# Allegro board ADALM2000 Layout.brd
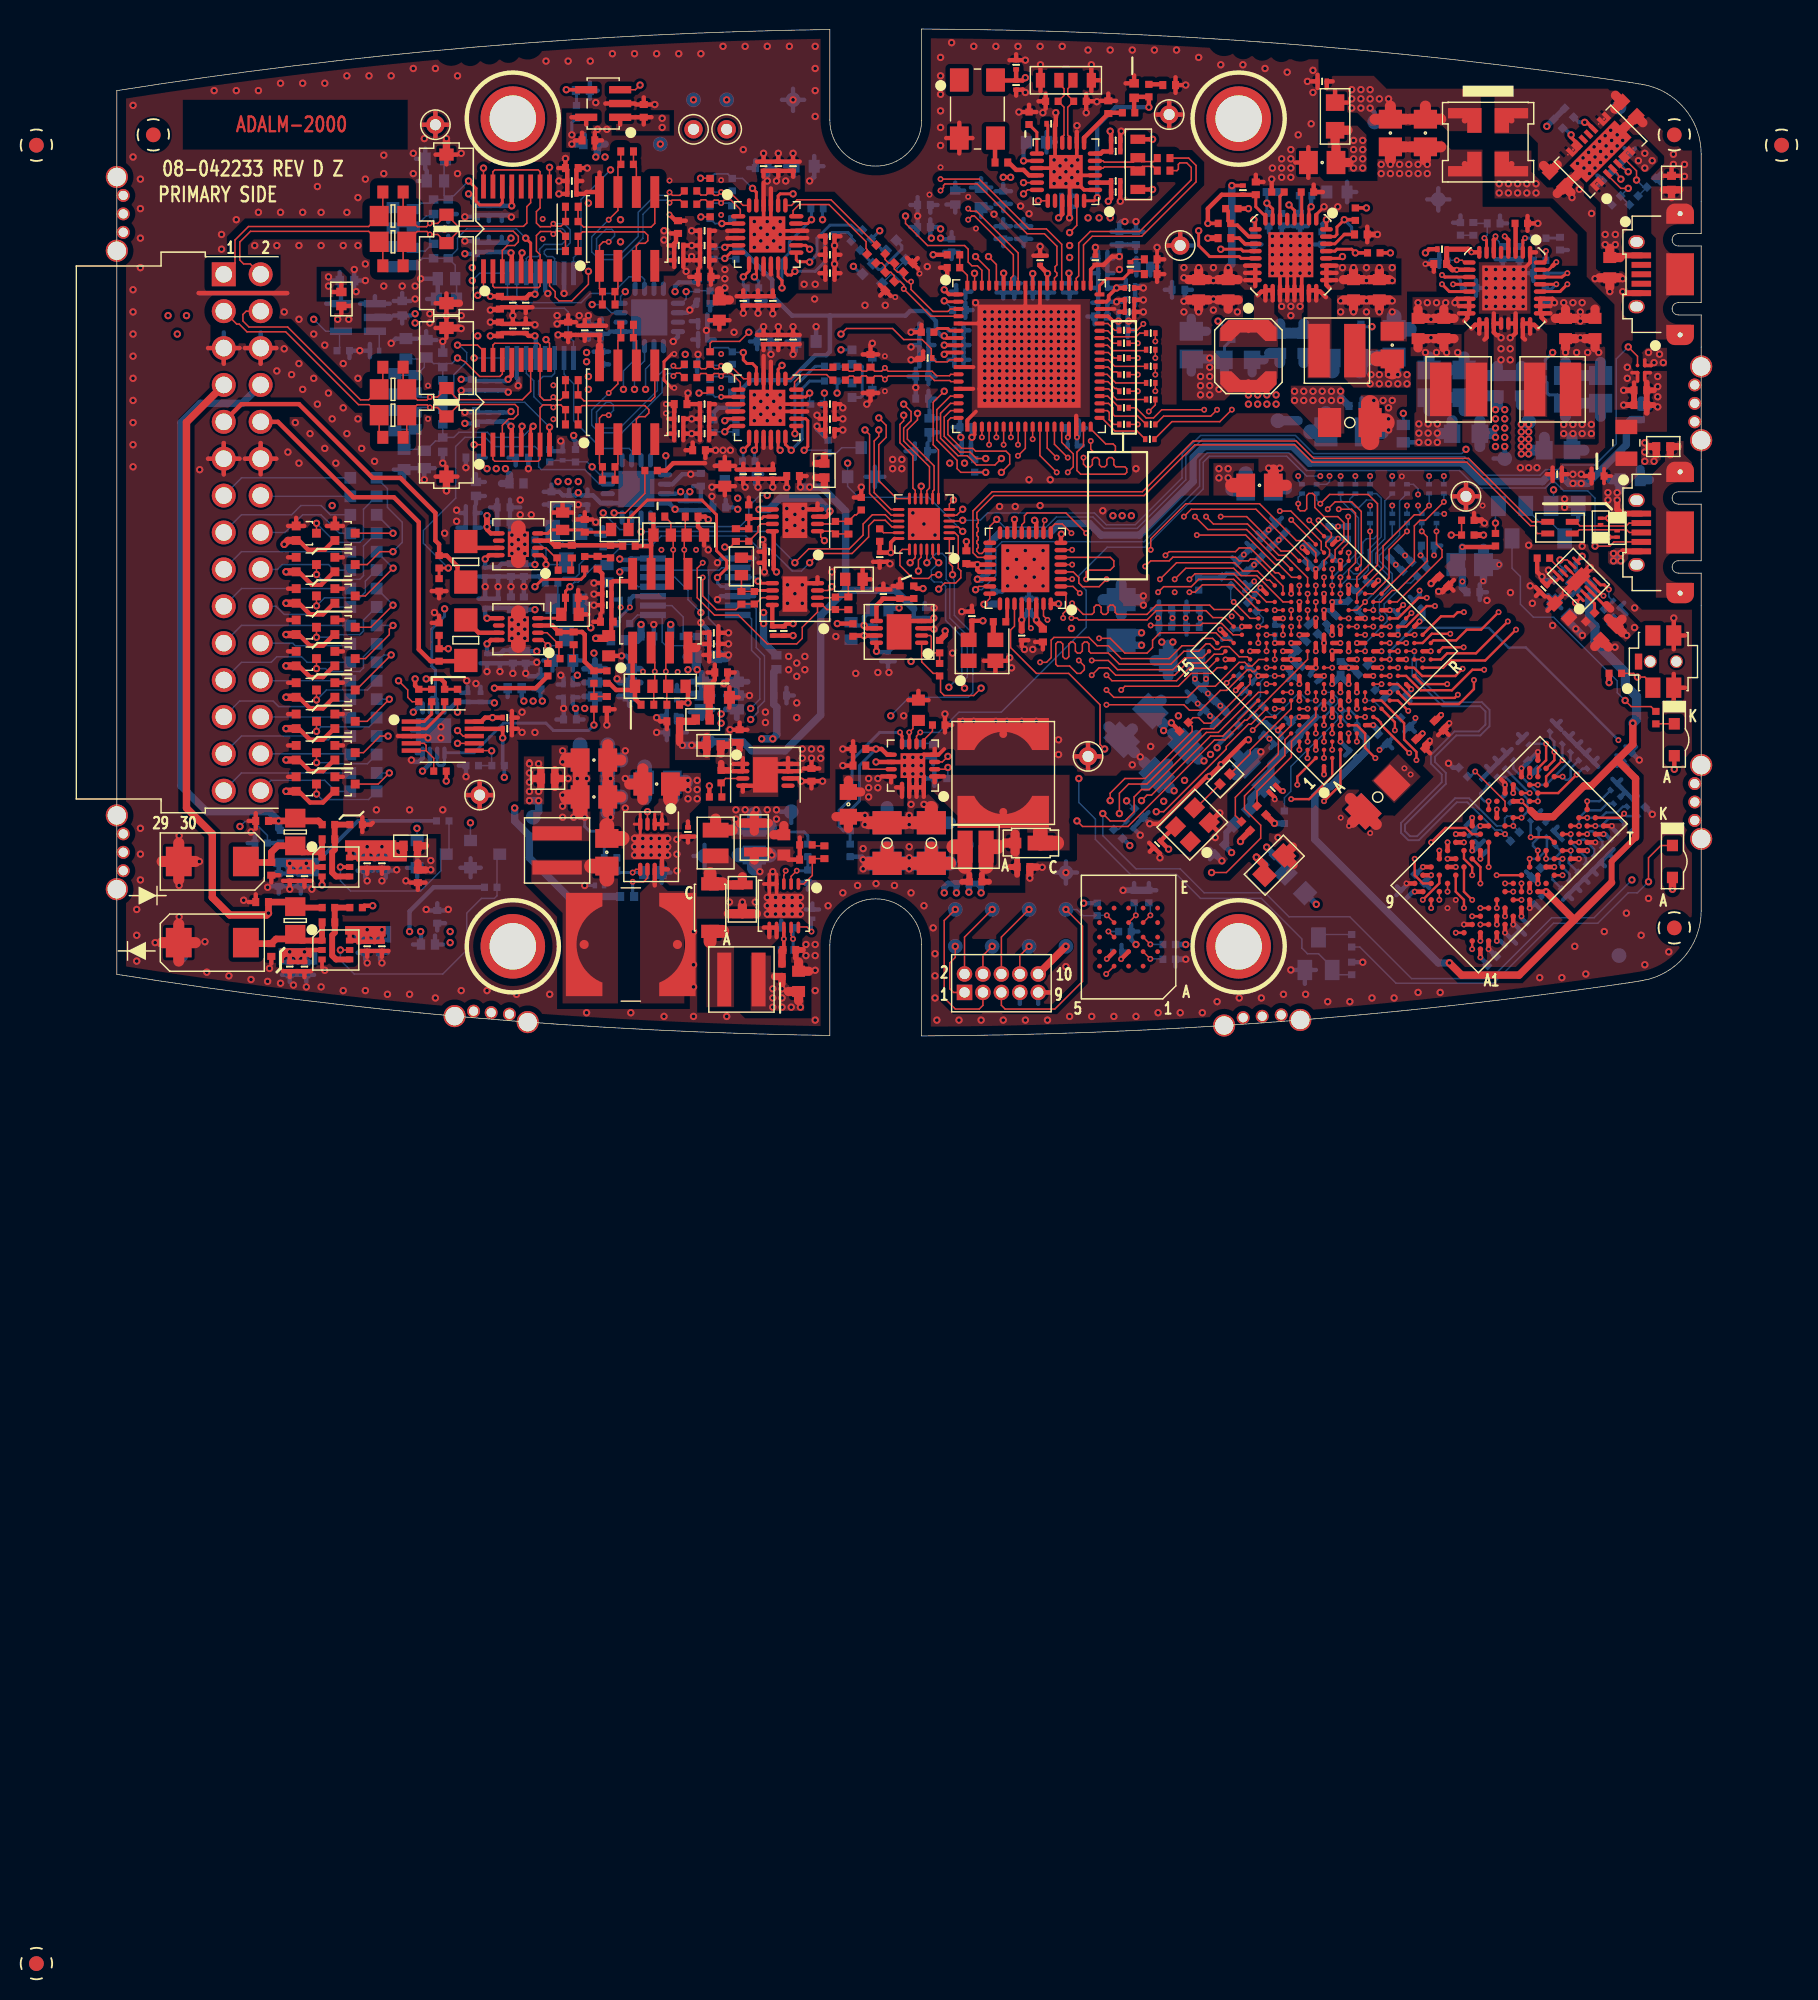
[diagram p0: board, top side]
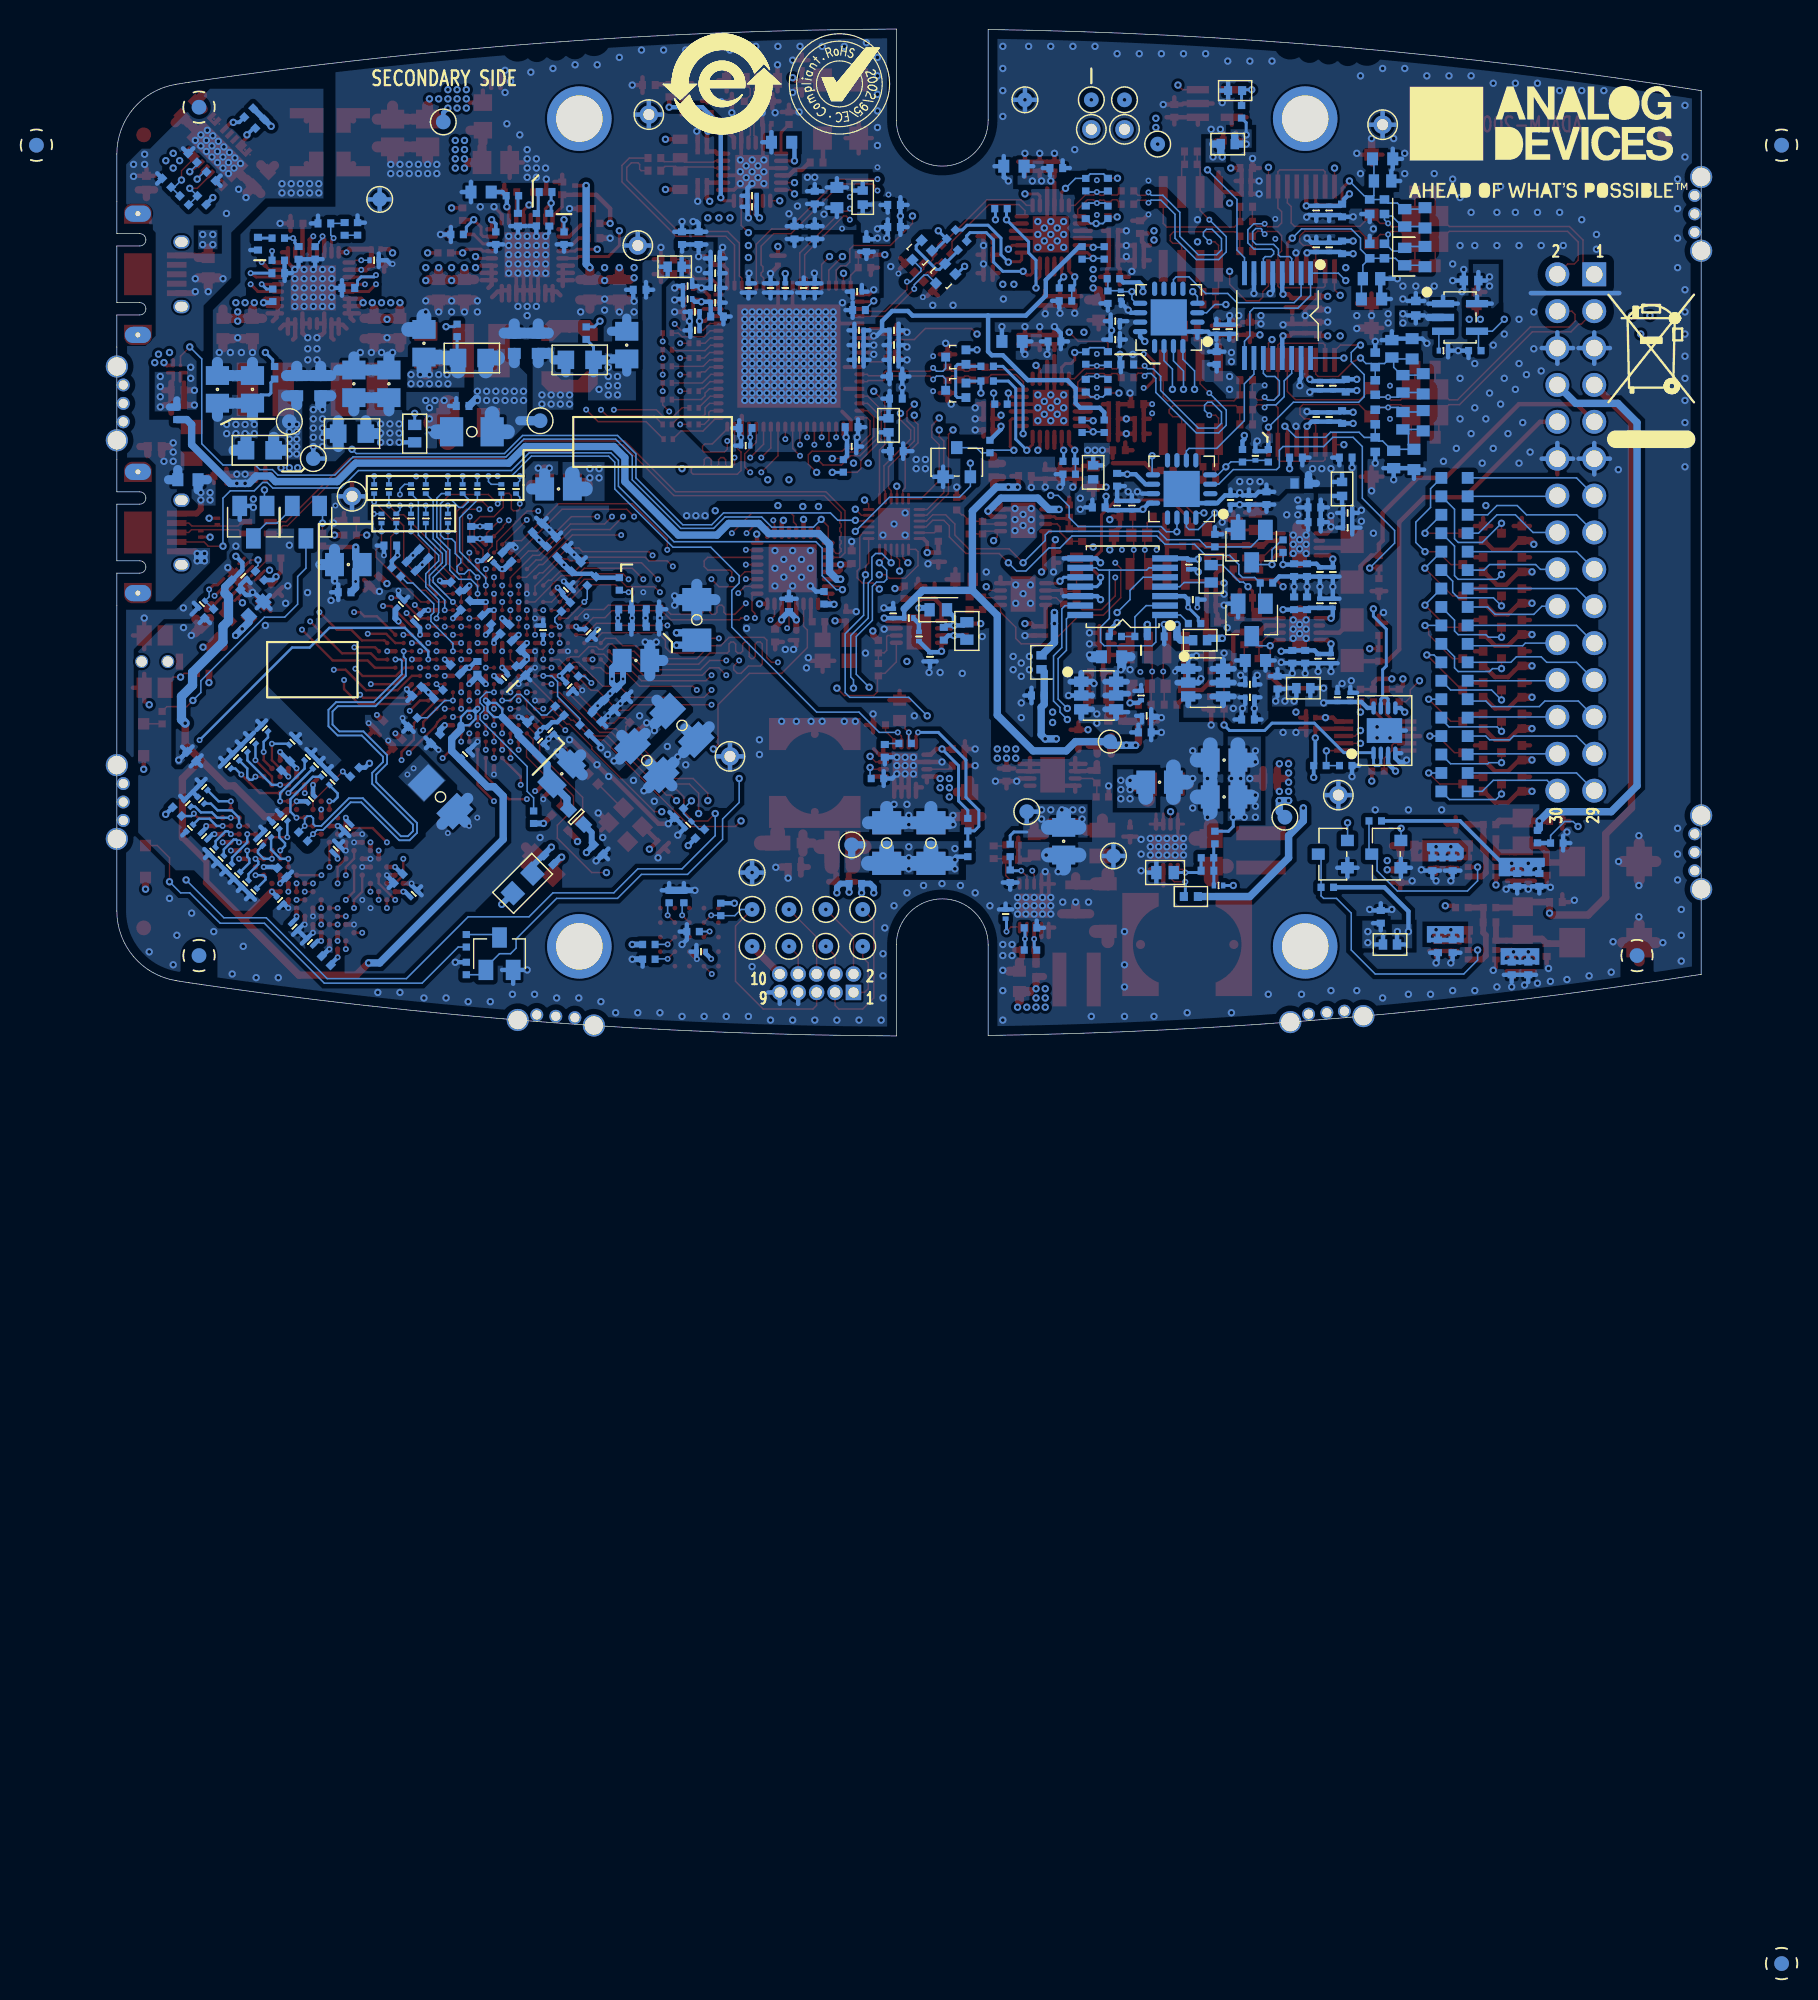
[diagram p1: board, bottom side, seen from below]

Outline 109.14 x 69.34 mm; copper layers: TOP, L2_GND, L3_PWR, L4_GND, L5_SIG, L6_SIG, L7_GND, L8_PWR, L9_GND, BOTTOM. Coordinates in mm from the lower left corner of the outline.
Outline path: 0,65.1 arc(24.48,68.08) 49.11,69.31 49.11,63.06 arc(52.28,59.9) 55.44,63.06 55.44,69.34 arc(79.87,68.37) 104.18,65.67 105.05,65.53 arc(107.98,63.88) 109.14,60.73 109.14,57.47 109.14,55.25 107.56,55.25 arc(107.26,55.12) 107.14,54.82 arc(107.26,54.52) 107.56,54.4 109.14,54.4 109.14,50.5 107.56,50.5 arc(107.26,50.37) 107.14,50.07 arc(107.26,49.77) 107.56,49.65 109.14,49.65 109.14,37.47 107.56,37.47 arc(107.26,37.34) 107.14,37.04 arc(107.26,36.74) 107.56,36.62 109.14,36.62 109.14,32.72 107.56,32.72 arc(107.26,32.59) 107.14,32.29 arc(107.26,31.99) 107.56,31.87 109.14,31.87 109.14,29.65 109.14,8.61 arc(107.98,5.45) 105.05,3.81 104.18,3.67 arc(79.87,0.97) 55.44,0 55.44,6.28 arc(52.28,9.44) 49.11,6.28 49.11,0.03 arc(24.48,1.26) 0,4.24 0,65.1

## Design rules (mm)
constraint set DEFAULT: min track width 0.102
net group ADC_SC1_N: nets ADC_SC1_N UNNAMED_31_ADA49402V2_I232__5
net group ADC_SC1_P: nets ADC_SC1_P UNNAMED_31_ADA49402V2_I232__4
net group ADC_SC2_N: nets ADC_SC2_N UNNAMED_32_ADA49402V2_I190__4
net group ADC_SC2_P: nets ADC_SC2_P UNNAMED_32_ADA49402V2_I190__5
net group DAC_AVG1: nets DAC_AVG1_N DAC_AVG1_P
net group DAC_AVG2: nets DAC_AVG2_N DAC_AVG2_P
net group DDR3_CK: nets DDR3_CK_N DDR3_CK_P
net group DDR3_DQS0: nets DDR3_DQS0_N DDR3_DQS0_P
net group DDR3_DQS1: nets DDR3_DQS1_N DDR3_DQS1_P
net group DP1: nets UNNAMED_31_ADG202N_I2_S UNNAMED_31_ADG202N_I19_S
net group DP4: nets UNNAMED_31_AD8066_I6_OUT UNNAMED_31_AD8066_I55_OUT
net group DP5: nets UNNAMED_31_ADA49402V2_I232__1 UNNAMED_31_ADA49402V2_I232__3
net group IN_1: nets UNNAMED_32_ADG202N_I25_S UNNAMED_32_ADG202N_I34_S
net group IN_1C: nets UNNAMED_32_AD8066_I42_OUT UNNAMED_32_AD8066_I82_OUT
net group IN_1D: nets UNNAMED_32_ADA49402V2_I190__1 UNNAMED_32_ADA49402V2_I190__2
net group IN_SC1: nets IN_SC1_N IN_SC1_P
net group IN_SC2: nets IN_SC2_N IN_SC2_P
net group MASTER_CLK_N: nets MASTER_CLK_N UNNAMED_36_ADF43609_I40_RFOUTB
net group MASTER_CLK_P: nets MASTER_CLK_P UNNAMED_36_ADF43609_I40_RFOUTA
net group PWR: nets VCCPLL VTTVREF
net group RX_CLK: nets RX_CLK UNNAMED_30_AD9963_I47_TRXCLK
net group RXD_0: nets RXD_0 UNNAMED_30_AD9963_I47_TRXD0
net group RXD_1: nets RXD_1 UNNAMED_30_AD9963_I47_TRXD1
net group RXD_2: nets RXD_2 UNNAMED_30_AD9963_I47_TRXD2
net group RXD_3: nets RXD_3 UNNAMED_30_AD9963_I47_TRXD3
net group RXD_4: nets RXD_4 UNNAMED_30_AD9963_I47_TRXD4
net group RXD_5: nets RXD_5 UNNAMED_30_AD9963_I47_TRXD5
net group RXD_6: nets RXD_6 UNNAMED_30_AD9963_I47_TRXD6
net group RXD_7: nets RXD_7 UNNAMED_30_AD9963_I47_TRXD7
net group RXD_8: nets RXD_8 UNNAMED_30_AD9963_I47_TRXD8
net group RXD_9: nets RXD_9 UNNAMED_30_AD9963_I47_TRXD9
net group RXD_10: nets RXD_10 UNNAMED_30_AD9963_I47_TRXD10
net group RXD_11: nets RXD_11 UNNAMED_30_AD9963_I47_TRXD11
net group RXIQ: nets RXIQ UNNAMED_30_AD9963_I47_TRXIQ
net group TX_CLK: nets TX_CLK UNNAMED_30_AD9963_I47_TXCLK
net group TXD_0: nets TXD_0 UNNAMED_30_AD9963_I47_TXD0
net group TXD_1: nets TXD_1 UNNAMED_30_AD9963_I47_TXD1
net group TXD_2: nets TXD_2 UNNAMED_30_AD9963_I47_TXD2
net group TXD_3: nets TXD_3 UNNAMED_30_AD9963_I47_TXD3
net group TXD_4: nets TXD_4 UNNAMED_30_AD9963_I47_TXD4
net group TXD_5: nets TXD_5 UNNAMED_30_AD9963_I47_TXD5
net group TXD_6: nets TXD_6 UNNAMED_30_AD9963_I47_TXD6
net group TXD_7: nets TXD_7 UNNAMED_30_AD9963_I47_TXD7
net group TXD_8: nets TXD_8 UNNAMED_30_AD9963_I47_TXD8
net group TXD_9: nets TXD_9 UNNAMED_30_AD9963_I47_TXD9
net group TXD_10: nets TXD_10 UNNAMED_30_AD9963_I47_TXD10
net group TXD_11: nets TXD_11 UNNAMED_30_AD9963_I47_TXD11
net group TXIQ: nets TXIQ UNNAMED_30_AD9963_I47_TXIQ
net group UART: nets UART_RX UART_TX
net group UNNAMED_31_AD8066_I6_NINV: nets UNNAMED_31_AD8066_I6_NINV UNNAMED_31_ADG202N_I19_D
net group UNNAMED_31_AD8066_I55_NINV: nets UNNAMED_31_AD8066_I55_NINV UNNAMED_31_ADG202N_I1_D
net group UNNAMED_32_AD8066_I42_NINV: nets UNNAMED_32_AD8066_I42_NINV UNNAMED_32_ADG202N_I164_S
net group UNNAMED_32_AD8066_I82_NINV: nets UNNAMED_32_AD8066_I82_NINV UNNAMED_32_ADG202N_I163_S
net group USB2: nets UNNAMED_45_CHOKE4P_I331_N2 UNNAMED_45_CHOKE4P_I331_N3
net group USB_OTG: nets USB_OTG_N USB_OTG_P
net group JTAG: nets JTAG_TCK JTAG_TDI JTAG_TDO JTAG_TMS
net group QSPI: nets PS_MIO01_500_QSPI0_SS_B PS_MIO02_500_QSPI0_IO0 PS_MIO03_500_QSPI0_IO1 PS_MIO04_500_QSPI0_IO2 PS_MIO05_500_QSPI0_IO3 PS_MIO06_500_QSPI0_SCLK
net group USB_ULPI: nets PS_MIO28_501_USB0_D4 PS_MIO29_501_USB0_DIR PS_MIO30_501_USB0_STP PS_MIO31_501_USB0_NXT PS_MIO32_501_USB0_D0 PS_MIO33_501_USB0_D1 PS_MIO34_501_USB0_D2 PS_MIO35_501_USB0_D3 PS_MIO36_501_USB0_CLK PS_MIO37_501_USB0_D5 PS_MIO38_501_USB0_D6 PS_MIO39_501_USB0_D7

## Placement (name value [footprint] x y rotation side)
A1  ADG612YRUZ  [TSSOP16]  27.53 43.63 0 top
A2  ADG611YRUZ  [TSSOP16]  29.18 49.6 0 bottom
A3  AD8066ARZ  [SO8]  35.15 55.57 0 top
A4  ADG612YRUZ  [TSSOP16]  27.53 55.57 0 top
A5  AD8066ARZ  [SO8]  35.15 43.63 0 top
A6  AD8657ACPZ  [QFN8_3X3_PAD2_44X1_7]  46.71 30.43 90 top
A7  AD8000YCPZ-R2  [QFN8_3X3_PAD1_75X1_45]  27.66 28.01 90 top
A8  AD8657ACPZ  [QFN8_3X3_PAD2_44X1_7]  46.71 35.51 90 top
A9  AD8000YCPZ-R2  [QFN8_3X3_PAD1_75X1_45]  27.66 33.86 90 top
A10  AD8058ARZ  [SO8]  37.44 29.28 0 top
A11  AD8657ACPZ  [QFN8_3X3_PAD2_44X1_7]  53.88 27.82 90 top
A12  ADA4805-1AKSZ  [SC70-6]  15.09 11.63 270 top
A13  AD8657ACPZ  [QFN8_3X3_PAD2_44X1_7]  21.82 21.03 180 bottom
A14  ADA4805-1AKSZ  [SC70-6]  15.09 5.92 270 top
C1  2200pF  [C0402]  56.23 19.63 270 bottom
C2  10uF  [C0603#2]  50.39 15.95 90 top
C3  1uF  [C0402]  51.15 18.62 180 top
C4  0.1uF  [C0201]  83.03 65.73 180 top
C5  22UF  [C0805H60]  83.03 60.14 180 top
C6  1uF  [C0402]  51.15 19.76 180 top
C7  0.1uF  [C0201]  65.82 40.65 0 bottom
C8  4.7UF  [C0402]  62.46 11.63 0 top
C9  47uF  [C1206H71]  56.11 13.28 90 top
C10  47uF  [C1206H71]  56.11 13.28 90 bottom
C11  47uF  [C1206H71]  53.06 13.28 90 bottom
C12  47uF  [C1206H71]  53.06 13.28 90 top
C13  0.01uF  [C0201]  47.92 8.39 90 bottom
C14  4.7UF  [C0402]  17.12 6.17 270 bottom
C15  15NF  [C0402]  48.74 12.65 90 top
C16  1uF  [C0402]  46.33 5.92 0 top
C17  10pF  [C0402]  47.47 12.14 180 top
C18  10uF  [C0603]  46.96 3.76 90 top
C19  22UF  [C0805H60]  37.31 17.47 180 bottom
C20  4.7UF  [C0402]  55.41 40.27 180 bottom
C21  4.7UF  [C0402]  73.12 51.38 0 bottom
C22  4.7UF  [C0402]  55.6 55.7 180 bottom
C23  22UF  [C0805H60]  43.09 9.41 270 top
C24  4.7UF  [C0402]  11.91 4.65 90 bottom
C25  4.7UF  [C0402]  69.06 54.94 90 bottom
C26  4.7UF  [C0402]  61.06 55.32 90 bottom
C27  4.7UF  [C0402]  58.52 41.92 180 bottom
C28  4.7UF  [C0402]  55.47 43.89 180 bottom
C29  1uF  [C0402]  70.2 54.94 90 bottom
C30  1uF  [C0402]  62.46 55.32 90 bottom
C31  1uF  [C0402]  67.79 49.54 180 bottom
C32  1uF  [C0402]  65.82 41.86 0 bottom
C33  1uF  [C0402]  55.47 45.41 180 bottom
C34  0.01uF  [C0201]  67.92 51.51 180 bottom
C35  0.01uF  [C0201]  58.14 51.25 0 bottom
C36  0.01uF  [C0201]  67.92 50.49 180 bottom
C37  0.01uF  [C0201]  69.31 48.59 0 bottom
C38  0.01uF  [C0201]  58.01 47.57 0 bottom
C39  0.01uF  [C0201]  69.76 51.51 0 top
C40  0.01uF  [C0201]  61.06 51.51 270 bottom
C41  0.01uF  [C0201]  69.76 49.86 0 top
C42  0.01uF  [C0201]  58.52 40.59 180 bottom
C43  0.01uF  [C0201]  58.01 48.59 0 bottom
C44  0.1uF  [C0201]  69.76 50.68 0 top
C45  0.01uF  [C0201]  67.41 53.41 90 top
C46  0.01uF  [C0201]  64.11 51.51 270 bottom
C47  1uF  [C0402]  18.13 6.17 270 bottom
C48  0.01uF  [C0201]  58.01 46.56 0 bottom
C49  0.1uF  [C0201]  69.82 50.75 0 bottom
C50  0.1uF  [C0201]  69.82 51.64 0 bottom
C51  0.1uF  [C0201]  65.63 51.51 270 bottom
C52  1000PF  [C0402]  60.93 60.14 0 top
C53  0.1uF  [C0201]  55.6 47.57 180 bottom
C54  0.1uF  [C0201]  67.92 52.52 180 bottom
C55  0.1uF  [C0201]  63.6 53.41 90 top
C56  0.1uF  [C0201]  52.8 30.43 90 top
C57  0.1uF  [C0201]  55.6 46.56 180 bottom
C58  0.1uF  [C0201]  67.92 53.54 180 bottom
C59  0.1uF  [C0201]  61.82 51.51 270 bottom
C60  0.1uF  [C0201]  69.31 49.86 0 bottom
C61  0.1uF  [C0201]  55.6 48.59 180 bottom
C62  0.1uF  [C0201]  63.09 51.51 270 bottom
C63  0.22UF  [C0402]  58.01 49.98 0 bottom
C64  820pF  [C0402]  71.22 52.46 0 top
C65  0.1uF  [C0201]  55.85 46.68 180 top
C66  0.068UF  [C0402H22]  71.22 53.48 0 top
C67  1uF  [C0402]  24.74 54.3 90 bottom
C68  0.1uF  [C0201]  25.63 54.3 90 bottom
C69  5-20PF  [CSML177W126H67]  22.71 58.62 90 top
C70  0.01uF  [C0201]  26.52 54.3 90 bottom
C71  5-20PF  [CSML177W126H67]  22.71 52.52 270 top
C72  33pF  [C0603]  19.02 58.11 0 top
C73  82PF  [C0603]  19.02 56.33 90 bottom
C74  0.001uF  [C0603]  21.94 60.4 180 bottom
C75  33pF  [C0603]  19.02 53.03 0 top
C76  82PF  [C0603]  19.02 53.67 270 bottom
C77  0.001uF  [C0603]  22.71 50.75 180 bottom
C78  0.01uF  [C0201]  26.52 56.84 270 bottom
C79  0.1uF  [C0201]  25.63 56.84 270 bottom
C80  1uF  [C0402]  24.74 56.84 270 bottom
C81  1uF  [C0402]  26.39 50.49 270 top
C82  0.1uF  [C0201]  27.28 50.49 270 top
C83  0.01uF  [C0201]  28.17 50.49 270 top
C84  0.01uF  [C0201]  28.17 48.71 90 top
C85  100pF  [C0402]  31.34 54.05 0 top
C86  0.1uF  [C0201]  27.28 48.71 90 top
C87  1uF  [C0402]  26.39 48.71 90 top
C88  100pF  [C0402]  31.34 57.1 0 top
C89  150pF  [C0402]  33.88 50.37 180 top
C90  1uF  [C0402]  33.37 46.68 270 bottom
C91  0.1uF  [C0201]  32.51 48.66 90 bottom
C92  150pF  [C0402]  35.15 60.91 180 top
C93  0.01uF  [C0201]  33.4 48.66 90 bottom
C94  4.7UF  [C0402]  52.17 27.7 270 bottom
C95  82PF  [C0603]  19.15 42.36 270 bottom
C96  0.1uF  [C0201]  26.9 21.16 0 top
C97  0.1uF  [C0201]  26.9 21.92 0 top
C98  1uF  [C0402]  38.66 55.7 90 top
C99  22UF  [C0805H60]  43.91 13.66 270 top
C100  0.1uF  [C0201]  38.71 54.43 0 top
C101  22UF  [C0805H60]  43.91 13.41 270 bottom
C102  0.01uF  [C0201]  38.71 53.41 0 top
C103  1pF  [C0402]  40.87 58.62 90 bottom
C104  1pF  [C0402]  42.39 56.72 270 bottom
C105  10uF  [C0603]  41.5 49.98 270 top
C106  10uF  [C0603]  47.34 59.89 180 bottom
C107  1uF  [C0402]  40.49 52.27 180 top
C108  1uF  [C0402]  44.42 59.76 0 bottom
C109  0.1uF  [C0201]  44.17 50.62 270 top
C110  0.1uF  [C0201]  49.12 53.79 180 top
C111  0.1uF  [C0201]  43.15 50.62 270 top
C112  0.1uF  [C0201]  49.12 52.52 180 top
C113  0.1uF  [C0201]  40.49 53.41 180 top
C114  0.1uF  [C0201]  46.58 59.89 270 top
C115  0.1uF  [C0201]  40.49 54.43 180 top
C116  0.1uF  [C0201]  45.57 59.89 270 top
C117  0.01uF  [C0201]  45.18 50.62 270 top
C118  0.01uF  [C0201]  49.12 55.06 180 top
C119  0.01uF  [C0201]  40.49 55.45 180 top
C120  0.01uF  [C0201]  44.55 59.89 270 top
C121  1pF  [C0402]  54.5 52.9 225 top
C122  10pF  [C0402]  53.25 52.9 225 top
C123  1pF  [C0402]  53.25 51.64 225 top
C124  1uF  [C0402]  24.74 42.62 90 bottom
C125  0.1uF  [C0201]  25.63 42.62 90 bottom
C126  5-20PF  [CSML177W126H67]  22.71 40.59 270 top
C127  0.01uF  [C0201]  26.52 42.62 90 bottom
C128  5-20PF  [CSML177W126H67]  22.71 46.68 90 top
C129  33pF  [C0603]  19.02 41.22 0 top
C130  82PF  [C0603]  19.15 44.9 90 bottom
C131  0.001uF  [C0603]  19.78 39.7 270 bottom
C132  33pF  [C0603]  19.02 46.05 0 top
C133  1uF  [C0402]  13.05 4.65 90 bottom
C134  0.001uF  [C0603]  19.91 47.32 90 bottom
C135  0.01uF  [C0201]  26.26 44.78 270 bottom
C136  0.1uF  [C0201]  25.37 44.78 270 bottom
C137  1uF  [C0402]  24.48 44.78 270 bottom
C138  1uF  [C0402]  29.94 37.03 270 bottom
C139  0.1uF  [C0201]  31.15 36.9 270 bottom
C140  0.01uF  [C0201]  32.42 36.9 270 bottom
C141  0.01uF  [C0201]  33.25 48.59 90 top
C142  0.1uF  [C0201]  32.23 48.59 90 top
C143  100pF  [C0402]  31.34 45.16 0 top
C144  1uF  [C0402]  31.09 48.71 90 top
C145  100pF  [C0402]  31.34 42.11 0 top
C146  150pF  [C0402]  35.15 48.97 180 top
C147  150pF  [C0402]  33.88 38.3 180 top
C148  1uF  [C0402]  38.83 43.51 0 top
C149  0.01uF  [C0201]  40.23 36.52 270 bottom
C150  0.1uF  [C0201]  39.22 36.52 270 bottom
C151  0.1uF  [C0201]  38.71 42.49 0 top
C152  1uF  [C0402]  40.23 38.3 90 bottom
C153  0.01uF  [C0201]  38.71 41.48 0 top
C154  10uF  [C0603]  41.88 38.55 270 top
C155  10uF  [C0603]  47.47 47.83 180 bottom
C156  1uF  [C0402]  40.1 40.33 180 top
C157  1uF  [C0402]  44.55 47.83 0 bottom
C158  0.1uF  [C0201]  43.15 38.68 270 top
C159  0.1uF  [C0201]  45.57 47.95 270 top
C160  0.1uF  [C0201]  44.17 38.68 270 top
C161  0.1uF  [C0201]  46.58 47.95 270 top
C162  1pF  [C0402]  40.87 46.68 90 bottom
C163  1pF  [C0402]  42.39 44.78 270 bottom
C164  0.1uF  [C0201]  40.49 42.49 180 top
C165  0.1uF  [C0201]  49.12 42.49 180 top
C166  0.1uF  [C0201]  40.49 41.48 180 top
C167  0.1uF  [C0201]  49.12 41.73 180 top
C168  0.01uF  [C0201]  40.49 43.51 180 top
C169  0.01uF  [C0201]  49.12 43.51 180 top
C170  0.01uF  [C0201]  45.18 38.68 270 top
C171  0.01uF  [C0201]  44.55 47.95 270 top
C172  1pF  [C0402]  51.92 46.49 270 top
C173  10pF  [C0402]  51.03 45.6 270 top
C174  1pF  [C0402]  51.92 44.71 270 top
C175  1uF  [C0402]  10.64 11.5 270 top
C176  10uF  [C0603]  45.95 13.15 270 top
C177  22UF  [C0805H60]  37.18 17.35 180 top
C178  10uF  [C0603]  85.19 51.38 270 top
C179  1uF  [C0402]  10.64 5.92 270 top
C180  0.1uF  [C0201]  39.34 14.04 270 top
C181  3PF  [C0402#2]  21.82 57.1 90 bottom
C182  33pF  [C0603]  55.22 22.43 90 top
C183  10uF  [C0603]  74.52 51.38 270 top
C184  220pF  [C0402]  34.01 11.38 180 bottom
C185  1PF  [C0402#2]  22.83 57.1 270 bottom
C186  22UF  [C0805H60]  33.75 12.65 90 top
C187  10uF  [C0603]  86.97 51.38 270 top
C188  0.01uF  [C0201]  33.25 10.36 180 bottom
C189  3PF  [C0402#2]  21.82 54.05 270 bottom
C190  10uF  [C0603]  76.55 51.38 270 top
C191  22UF  [C0805H60]  32.87 19 0 top
C192  22UF  [C0805H60]  32.87 16.46 0 top
C193  0.047UF  [C0402]  85.7 55.19 180 top
C194  0.047UF  [C0402]  76.3 54.94 0 top
C195  22UF  [C0805H60]  32.87 19 0 bottom
C196  1uF  [C0402]  78.46 58.37 90 top
C197  33pF  [C0603]  84.05 58.11 0 bottom
C198  22UF  [C0805H60]  32.87 16.46 0 bottom
C199  120pF  [C0402]  79.35 56.21 270 bottom
C200  0.018uF  [C0402]  14.58 7.82 180 top
C201  0.018uF  [C0402]  14.58 13.54 180 top
C202  0.1uF  [C0201]  17.24 6.17 270 top
C203  0.0022uF  [C0402]  79.6 58.11 0 bottom
C204  1uF  [C0402]  55.6 57.22 180 bottom
C205  1uF  [C0402]  41.5 36.4 180 bottom
C206  1uF  [C0402]  36.55 27.51 0 bottom
C207  0.0012uF  [C0402]  81.51 56.21 270 bottom
C208  47uF  [C0805H60]  87.98 47.7 90 bottom
C209  1uF  [C0402]  22.07 8.2 90 bottom
C210  1uF  [C0402]  27.91 39.82 0 bottom
C211  1uF  [C0402]  24.48 39.82 180 bottom
C212  1uF  [C0402]  45.69 23.44 0 bottom
C213  1uF  [C0402]  29.18 24.33 90 bottom
C214  1uF  [C0402]  20.74 11 270 top
C215  22UF  [C0805H60]  74.01 47.57 90 bottom
C216  0.1uF  [C0201]  11.91 4.77 90 top
C217  4.7UF  [C0402]  47.85 17.98 270 top
C218  4.7UF  [C0402]  42.9 20.65 90 top
C219  0.1uF  [C0201]  30.71 39.95 90 bottom
C220  0.1uF  [C0201]  39.98 51 270 bottom
C221  1uF  [C0402]  46.58 38.55 180 top
C222  1uF  [C0402]  38.33 21.66 180 top
C223  12PF  [C0402#2]  70.08 65.1 90 top
C224  0.1uF  [C0201]  61.95 66.88 90 top
C225  0.01uF  [C0201]  61.95 65.48 270 top
C226  10uF  [C0603]  59.54 57.73 270 bottom
C227  0.01uF  [C0201]  64.36 62.81 0 top
C228  1uF  [C0402]  61.06 57.73 270 bottom
C229  0.1uF  [C0201]  68.81 60.91 0 top
C230  10uF  [C0603]  63.35 61.54 0 bottom
C231  0.1uF  [C0201]  65.38 57.86 0 bottom
C232  0.1uF  [C0201]  68.81 58.11 0 top
C233  0.01uF  [C0201]  68.81 61.67 0 top
C234  0.01uF  [C0201]  68.81 58.87 0 top
C235  0.01uF  [C0201]  65.38 57.1 0 bottom
C236  100pF  [C0402]  72.11 59.59 0 top
C237  100pF  [C0402]  72.11 60.45 0 top
C238  220pF  [C0402]  72.49 65.48 0 top
C239  4.7pF  [C0402]  68.3 63.95 90 top
C240  0.1uF  [C0201]  52.55 32.97 270 top
C241  47uF  [C0805H60]  87.86 47.57 90 top
C242  10uF  [C0603]  33.88 26.87 270 top
C243  10uF  [C0603]  41.5 23.31 180 top
C244  1uF  [C0402]  33.75 28.52 180 top
C245  1uF  [C0402]  41.63 25.03 180 top
C246  0.1uF  [C0201]  33.75 29.66 180 top
C247  0.1uF  [C0201]  41.12 27 180 top
C248  3.9pF  [C0402]  38.33 22.81 0 top
C249  3.9pF  [C0402]  39.6 35.76 0 top
C250  0.1uF  [C0201]  33.75 31.19 180 top
C251  0.1uF  [C0201]  41.12 26.24 180 top
C252  3.9pF  [C0402]  36.55 22.81 180 top
C253  0.01uF  [C0201]  33.75 30.43 180 top
C254  0.01uF  [C0201]  41.12 27.76 180 top
C255  3.9pF  [C0402]  37.31 35.76 180 top
C256  3.9pF  [C0402]  33.75 22.93 270 top
C257  3.9pF  [C0402]  33.12 32.59 270 top
C258  4.7UF  [C0402]  28.17 26.11 270 bottom
C259  4.7UF  [C0402]  26.64 35.38 180 bottom
C260  4.7UF  [C0402]  31.34 30.17 0 top
C261  4.7UF  [C0402]  32.23 35.13 90 top
C262  1uF  [C0402]  27.28 26.11 270 bottom
C263  1uF  [C0402]  27.15 29.79 270 bottom
C264  0.1uF  [C0201]  26.39 25.98 270 bottom
C265  0.1uF  [C0201]  26.26 29.79 270 bottom
C266  1pF  [C0402]  31.47 27.38 270 top
C267  1pF  [C0402]  31.34 33.35 270 top
C268  0.01uF  [C0201]  25.5 25.98 270 bottom
C269  0.01uF  [C0201]  25.37 29.79 270 bottom
C270  4.7UF  [C0402]  28.04 32.08 270 bottom
C271  4.7UF  [C0402]  28.04 29.79 270 bottom
C272  1uF  [C0402]  27.15 32.08 270 bottom
C273  1uF  [C0402]  26.64 36.4 180 bottom
C274  0.1uF  [C0201]  26.26 31.95 270 bottom
C275  0.1uF  [C0201]  24.36 36.01 0 bottom
C276  0.01uF  [C0201]  25.37 31.95 270 bottom
C277  0.01uF  [C0201]  24.36 35 0 bottom
C278  10uF  [C0603]  80.11 47.7 90 bottom
C279  10uF  [C0603]  81.76 47.7 90 bottom
C280  2.2uF  [C0402]  104.95 44.46 180 top
C281  4.7UF  [C0402]  104.95 43.44 180 top
C282  0.01uF  [C0201]  18.26 6.17 270 top
C283  0.01uF  [C0201]  12.93 4.77 90 top
C284  1uF  [C0402]  38.33 20.9 180 bottom
C285  1uF  [C0402]  31.21 21.79 180 bottom
C286  0.1uF  [C0201]  38.2 22.04 180 bottom
C287  0.1uF  [C0201]  31.09 23.31 180 bottom
C288  0.1uF  [C0201]  45.95 27.89 270 top
C289  10uF  [C0603]  40.61 26.11 0 bottom
C290  0.01uF  [C0201]  45.18 27.89 270 top
C291  10uF  [C0603]  30.71 25.85 180 bottom
C292  0.1uF  [C0201]  38.58 23.44 270 bottom
C293  0.1uF  [C0201]  31.09 24.2 180 bottom
C294  0.1uF  [C0201]  44.93 32.59 180 top
C295  0.01uF  [C0201]  44.93 33.35 180 top
C296  0.1uF  [C0201]  35.28 32.46 270 bottom
C297  1uF  [C0402]  10.01 14.81 180 top
C298  0.01uF  [C0201]  53.12 26.11 270 bottom
C299  0.1uF  [C0201]  35.02 30.05 180 bottom
C300  0.1uF  [C0201]  25.06 23.31 90 bottom
C301  0.01uF  [C0201]  24.17 23.31 90 bottom
C302  4.7UF  [C0402]  42.64 34.49 270 top
C303  4.7UF  [C0402]  50.39 35 270 top
C304  4.7UF  [C0402]  50.39 29.79 270 top
C305  4.7UF  [C0402]  43.03 30.17 270 top
C306  0.1uF  [C0201]  53.88 27.51 90 bottom
C307  0.1uF  [C0201]  54.58 28.78 0 bottom
C308  1uF  [C0402]  10.01 9.22 180 top
C309  0.01uF  [C0201]  55.66 29.09 270 bottom
C310  1uF  [C0402]  36.29 63.7 90 top
C311  1uF  [C0402]  32.48 61.67 0 top
C312  10uF  [C0603]  99.22 59 315 top
C313  10uF  [C0603]  104.18 63.83 315 top
C314  4.7UF  [C0402]  17.12 11.82 270 bottom
C315  4.7UF  [C0402]  11.15 10.74 90 bottom
C316  1uF  [C0402]  18.51 11.82 270 bottom
C317  1uF  [C0402]  12.67 10.74 90 bottom
C318  0.1uF  [C0201]  17.24 11.88 270 top
C319  0.1uF  [C0201]  11.91 11 90 top
C320  47uF  [C0805H60]  90.14 62.18 270 top
C321  47uF  [C0805H60]  87.73 62.18 270 top
C322  0.01uF  [C0201]  18.26 11.88 270 top
C323  0.01uF  [C0201]  12.93 11 90 top
C324  0.1uF  [C0201]  99.22 38.68 180 top
C325  10uF  [C0603]  104.24 38.3 0 bottom
C326  10uF  [C0603]  102.84 52.91 270 top
C327  1uF  [C0402#2]  19.66 50.11 90 bottom
C328  0.01uF  [C0201]  17.75 47.19 180 bottom
C329  1uF  [C0402#2]  15.85 52.02 0 bottom
C330  1uF  [C0402]  31.34 59.76 180 top
C331  0.1uF  [C0201]  31.34 58.87 180 top
C332  0.01uF  [C0201]  31.34 57.99 180 top
C333  1uF  [C0402]  39.53 46.24 0 bottom
C334  0.1uF  [C0201]  40.36 49.22 0 bottom
C335  0.01uF  [C0201]  40.36 47.95 0 bottom
C336  1PF  [C0402#2]  22.83 54.05 90 bottom
C337  3PF  [C0402#2]  22.45 42.62 270 bottom
C338  1PF  [C0402#2]  22.45 40.71 270 bottom
C339  3PF  [C0402#2]  22.45 44.65 90 bottom
C340  1PF  [C0402#2]  22.45 46.56 90 bottom
C579  0.1uF  [C0201]  71.66 13.2 225 top
C588  0.1uF  [C0201]  69.78 14.55 315 bottom
C589  0.1uF  [C0201]  68.9 5.8 0 bottom
C595  100uF  [C1206H71]  72.63 18.96 225 bottom
C596  4.7UF  [C0402]  76.09 21.96 225 bottom
C597  0.47uF  [C0402]  72.22 29.38 180 bottom
C598  0.1uF  [C0201]  79.98 20.33 225 bottom
C599  0.01uF  [C0201]  79.27 21.04 225 bottom
C600  100uF  [C1206H71]  86.86 16.45 225 top
C607  4.7UF  [C0402]  87.19 20.47 315 bottom
C614  0.47uF  [C0402]  91.41 31.33 315 top
C615  4.7UF  [C0402]  103.99 19.25 45 bottom
C616  0.47uF  [C0402]  89.81 20.12 315 top
C617  0.47uF  [C0402]  91.08 21.39 315 top
C618  0.47uF  [C0402]  88.47 23.73 315 bottom
C626  0.1uF  [C0201]  79.62 17 225 top
C633  0.01uF  [C0201]  89.57 29.73 135 bottom
C637  100uF  [C1206H71]  86.84 16.46 225 bottom
C639  4.7UF  [C0402]  97.51 18.62 135 bottom
C641  4.7UF  [C0402]  89.75 10.85 315 bottom
C643  0.47uF  [C0402]  94.71 5.19 45 bottom
C644  0.01uF  [C0201]  103.29 29.73 315 bottom
C645  0.47uF  [C0402]  97.76 11.25 225 bottom
C647  0.1uF  [C0201]  93.22 14.32 315 bottom
C648  0.01uF  [C0201]  98.27 30.81 45 top
C649  0.1uF  [C0201]  94.07 12.9 135 bottom
C650  0.01uF  [C0201]  97.89 9.36 45 bottom
C651  0.1uF  [C0201]  95.84 6.46 45 bottom
C652  0.1uF  [C0201]  96.9 7.52 225 bottom
C654  0.01uF  [C0201]  95.76 16.3 135 bottom
C655  0.1uF  [C0201]  103.12 13.75 45 bottom
C656  10uF  [C0603]  99.54 29.28 135 top
C657  0.22UF  [C0402]  100.94 31.06 225 bottom
C658  0.1uF  [C0201]  88.69 9.79 135 bottom
C659  10uF  [C0603]  99.54 29.41 135 bottom
C660  0.01uF  [C0201]  100.43 31.7 225 bottom
C662  10uF  [C0603]  102.75 27.76 225 top
C663  100uF  [C1206H71]  84.94 42.24 0 top
C664  47uF  [C0805H60]  73.38 25.85 180 bottom
C665  4.7UF  [C0402]  82.4 28.01 315 bottom
C666  4.7UF  [C0402]  72.22 28.18 180 bottom
C667  0.47uF  [C0402]  85.32 43.38 0 bottom
C668  0.47uF  [C0402]  83.67 28.65 45 bottom
C669  0.47uF  [C0402]  84.3 25.35 90 bottom
C670  100uF  [C1206H71]  84.68 41.6 0 bottom
C671  0.47uF  [C0402]  85.13 29.66 315 bottom
C672  4.7UF  [C0402]  85.82 25.22 225 bottom
C673  0.47uF  [C0402]  81.63 26.87 45 bottom
C674  0.47uF  [C0402]  81.32 25.16 225 bottom
C675  4.7UF  [C0402]  75.97 12.83 225 bottom
C676  100uF  [C1206H71]  69.19 28.65 90 bottom
C678  47uF  [C0805H60]  93.19 32.46 0 bottom
C679  4.7UF  [C0402]  74.13 28.17 180 bottom
C680  47uF  [C0805H60]  78.49 18.05 135 bottom
C683  0.47uF  [C0402]  74.13 29.37 180 bottom
C684  0.47uF  [C0402]  79.39 12.12 225 bottom
C686  0.47uF  [C0402]  81.18 21.25 135 bottom
C688  0.1uF  [C0201]  82.46 24.65 135 bottom
C692  0.01uF  [C0201]  85.15 19.41 315 bottom
C696  47uF  [C0805H60]  78.71 37.92 0 top
C697  47uF  [C0805H60]  78.71 37.67 0 bottom
C698  4.7UF  [C0402]  77.49 32.3 135 bottom
C699  4.7UF  [C0402]  93.44 30.55 0 bottom
C700  4.7UF  [C0402]  79.19 34 135 bottom
C701  4.7UF  [C0402]  90.3 33.76 0 bottom
C702  0.47uF  [C0402]  78.48 33.29 135 bottom
C703  0.47uF  [C0402]  82.27 32.97 45 bottom
C704  0.47uF  [C0402]  88.87 32.33 45 bottom
C705  0.47uF  [C0402]  84.72 34.64 90 bottom
C706  0.47uF  [C0402]  80.18 34.99 135 bottom
C707  0.47uF  [C0402]  83.52 34.64 90 bottom
C708  0.47uF  [C0402]  87.98 33.22 45 bottom
C709  0.47uF  [C0402]  85.82 30.93 45 bottom
C710  0.1uF  [C0201]  79.77 27.94 90 bottom
C711  0.1uF  [C0201]  83.41 32.84 45 bottom
C712  0.01uF  [C0201]  78.21 30.73 135 bottom
C713  0.01uF  [C0201]  88.49 28.78 315 bottom
C737  10uF  [C0603]  99.79 48.71 270 top
C738  10uF  [C0603]  91.41 48.71 270 top
C740  10uF  [C0603]  101.83 48.71 270 top
C742  10uF  [C0603]  89.63 48.71 270 top
C745  0.047UF  [C0402]  98.02 52.52 0 bottom
C746  0.047UF  [C0402]  93.19 51.51 180 bottom
C748  1uF  [C0402]  91.16 53.16 180 top
C751  150pF  [C0402]  96.62 53.92 90 bottom
C753  5.6NF  [C0402H22]  99.41 54.56 90 bottom
C754  47uF  [C0805H60]  90.4 44.9 90 bottom
C756  180PF  [C0402]  94.84 55.95 180 bottom
C757  0.0033uF  [C0402]  93.44 55.57 270 bottom
C758  47uF  [C0805H60]  92.81 44.9 90 bottom
C761  47uF  [C0805H60]  102.21 44.52 90 bottom
C762  47uF  [C0805H60]  99.79 44.52 90 bottom
C769  10uF  [C0603]  95.1 44.78 90 bottom
C774  10uF  [C0603]  96.75 44.78 90 bottom
C788  100uF  [C1206H71]  70.2 21.39 225 bottom
C789  4.7UF  [C0402]  75.24 22.81 225 bottom
C790  0.47uF  [C0402]  74.39 23.66 225 bottom
C792  0.1uF  [C0201]  76.65 27.79 225 bottom
C793  0.01uF  [C0201]  77.95 24.08 225 bottom
C795  0.1uF  [C0201]  58.9 28.9 270 top
C801  2.2uF  [C0402]  58.52 32.97 90 top
C803  0.01uF  [C0201]  62.33 27.57 270 top
C805  1uF  [C0402]  63.79 27.57 270 top
C807  1uF  [C0402]  62.84 29.66 90 bottom
CALIB_REF1  TESTPAD  [TPSMC40]  39.72 64.46 180 bottom
CALIB_REF2  TESTPAD  [TPSMC40]  42.01 64.46 180 bottom
D1  SMBJ5340B-TP  [DO214AA]  6.58 12.01 180 top
D2  DB3S406F0L  [SC89]  15.72 32.46 270 top
D3  DB3S406F0L  [SC89]  15.72 34.62 270 top
D4  DB3S406F0L  [SC89]  15.72 30.3 270 top
D5  DB3S406F0L  [SC89]  15.72 28.14 270 top
D6  DB3S406F0L  [SC89]  15.72 25.98 270 top
D7  DB3S406F0L  [SC89]  15.72 23.82 270 top
D8  DB3S406F0L  [SC89]  15.72 21.66 270 top
D9  DB3S406F0L  [SC89]  15.72 19.5 270 top
D10  DB3S406F0L  [SC89]  15.72 17.35 270 top
D11  DB3S406F0L  [SC89]  13.05 17.35 270 top
D12  DB3S406F0L  [SC89]  13.05 19.5 270 top
D13  DB3S406F0L  [SC89]  13.05 21.66 270 top
D14  DB3S406F0L  [SC89]  13.05 23.82 270 top
D15  DB3S406F0L  [SC89]  13.05 25.98 270 top
D16  DB3S406F0L  [SC89]  13.05 28.14 270 top
D17  DB3S406F0L  [SC89]  13.05 30.3 270 top
D18  DB3S406F0L  [SC89]  13.05 32.46 270 top
D19  DB3S406F0L  [SC89]  13.05 34.62 270 top
D20  DB3S406F0L  [SC89]  53.84 53.94 45 bottom
D21  DB3S406F0L  [SC89]  52.22 52.32 45 bottom
D22  DB3S406F0L  [SC89]  51.34 46.75 90 bottom
D23  DB3S406F0L  [SC89]  51.34 44.46 90 bottom
D24  PD3S140-7  [POWERDI323]  62.96 13.28 180 top
D25  MBR130LSFT1G  [SOD123FL]  40.87 8.84 270 top
D26  SMBJ5340B-TP  [DO214AA]  6.58 6.42 0 top
D739  SESD0201X1UN-0020-09  [D0201]  103.35 34.57 270 top
D741  SESD0201X1UN-0020-09  [D0201]  102.21 35.43 90 top
DS11  LTST-S220TBKT  [LED0804]  107.29 20.39 270 top
DS12  LTST-S220TBKT  [LED0804]  107.16 12.01 270 top
E1  220OHM  [L0402]  32.61 61.41 180 bottom
E2  220OHM  [L0402]  55.98 42.05 90 bottom
E3  220OHM  [L0402]  70.71 52.97 180 bottom
E4  100OHM  [L0805]  83.92 63.32 270 top
E5  220OHM  [L0402]  15.47 50.75 90 top
E8  220OHM  [L0402]  29.69 17.73 180 top
E9  220OHM  [L0402]  41.88 38.81 90 bottom
E10  220OHM  [L0402]  34.52 27.25 180 bottom
E12  220OHM  [L0402]  57.76 57.73 90 bottom
E13  220OHM  [L0402]  24.74 37.67 270 bottom
E14  220OHM  [L0402]  45.44 25.73 90 bottom
E15  220OHM  [L0402]  27.53 38.05 0 bottom
E16  220OHM  [L0402]  21.44 6.3 180 bottom
E17  220OHM  [L0402]  27.4 23.95 180 bottom
E18  220OHM  [L0402]  20.23 13.09 180 top
E19  220OHM  [L0402]  41.12 20.01 180 top
E21  100OHM  [L0805]  77.25 46.56 0 bottom
E22  220OHM  [L0402]  48.74 38.94 90 top
E24  220OHM  [L0402]  40.36 21.79 0 top
E26  100OHM  [L0805]  84.68 46.68 180 bottom
E677  600OHMS  [L0603]  77.5 15.08 45 bottom
E682  100OHM  [L0805]  81.18 10.5 135 bottom
E687  100OHM  [L0805]  79.73 11.76 225 top
E767  100OHM  [L0805]  92.94 41.48 0 bottom
E768  100OHM  [L0805]  99.29 40.33 180 bottom
F1  0.5A  [F0805]  103.99 40.84 270 top
GND_4  TESTPAD  [TPC50D30]  66.9 19.25 180 bottom
GND_5  TESTPAD  [TPC50D30]  92.94 37.16 180 bottom
GND_6  TESTPAD  [TPC50D30]  73.25 54.43 180 bottom
GND_7  TESTPAD  [TPSMC40]  46.58 64.46 180 bottom
GND_8  TESTPAD  [TPSMC40]  65.38 11.25 180 bottom
GND_9  TESTPAD  [TPSMC40]  91.03 57.6 180 bottom
GND_10  TESTPAD  [TPSMC40]  40.49 12.39 180 bottom
IO3  TESTPAD  [TPSMC40]  65.38 8.71 180 bottom
L1  90OHMS AT 100MEGHZ  [L0805-4PH39]  99.41 35 0 top
L2  3UH  [LSMSQ228H118_A]  61.06 18.11 270 top
L3  10UH  [LSMSQ287H161_A]  35.41 6.3 180 top
L4  180NH  [LSMSQ79H41]  59.15 13.03 180 top
L5  600nH  [LSMSQ157H47]  30.33 12.77 90 top
L6  4.7uH  [LSMSQ157H122]  43.03 3.88 180 top
L7  110nH  [L9075]  41.25 13.28 90 top
L8  5.6UH  [LSMSQ154H47_A]  77.95 46.81 270 top
L9  1uH  [LSMSQ157H83]  84.05 47.19 0 top
L10  190OHMS AT 100MEGHZ  [L2020_A]  94.46 61.54 180 top
L13  270nH  [L7144]  66.5 65.81 180 top
L14  270nH  [L7144]  64.26 65.81 0 top
L15  220NH  [L7144]  70.33 58.93 270 top
L16  220NH  [L7144]  70.33 61.11 90 top
L520  1.5uH  [LSMSQ157H83]  92.43 44.52 180 top
L521  1.5uH  [LSMSQ157H83]  98.91 44.52 0 top
NOREF  -  [unnamed]  77.59 1.26 180 top
NOREF#2  -  [unnamed]  109.14 18.65 0 top
NOREF#3  -  [unnamed]  108.69 17.38 180 top
NOREF#4  -  [unnamed]  0.44 12.64 0 top
NOREF#5  -  [#2]  -1.27 -56.7 0 top
NOREF#6  -  [#2]  -1.27 59.15 0 top
NOREF#7  -  [unnamed]  0.44 13.91 0 top
NOREF#8  -  [unnamed]  24.58 1.71 180 top
NOREF#9  -  [#2]  -8.54 69.34 0 top
NOREF#10  -  [unnamed]  107.29 7.44 0 top
NOREF#11  -  [unnamed]  0.44 56.61 0 top
NOREF#12  -  [#2]  -5.54 -68.88 0 top
NOREF#13  -  [#2]  -98.72 -141.99 0 top
NOREF#14  -  [unnamed]  80.21 1.45 180 top
NOREF#15  -  [unnamed]  81.52 1.1 0 top
NOREF#16  -  [#2]  -5.54 -68.88 0 top
NOREF#17  -  [unnamed]  108.69 44.83 180 top
NOREF#18  -  [#2]  0 155.05 0 top
NOREF#19  -  [unnamed]  0.44 55.34 0 top
NOREF#20  -  [unnamed]  0.44 57.88 0 top
NOREF#21  -  [#2]  -1.27 -17.81 0 top
NOREF#22  -  [#2]  -98.72 -141.99 0 top
NOREF#23  -  [unnamed]  0 15.18 0 top
NOREF#24  -  [unnamed]  77.28 63.17 180 top
NOREF#25  -  [#2]  117.68 -71.88 90 top
NOREF#26  -  [#2]  -5.54 -68.88 0 top
NOREF#27  -  [#2]  115.99 67.29 0 top
NOREF#28  -  [#2]  0 155.05 0 top
NOREF#29  -  [#2]  -88.22 48.51 0 top
NOREF#30  -  [#2]  -1.27 54.07 0 top
NOREF#31  -  [unnamed]  0 59.15 0 top
NOREF#32  -  [unnamed]  76.28 0.72 0 top
NOREF#33  -  [unnamed]  -5.54 -63.88 0 top
NOREF#34  -  [#2]  49.11 150.84 0 top
NOREF#35  -  [unnamed]  2.51 62.05 0 top
NOREF#36  -  [#2]  27.28 156.98 0 top
NOREF#37  -  [#2]  -5.54 66.34 0 top
NOREF#38  -  [#2]  0 -67.64 0 top
NOREF#39  -  [#2]  -1.27 -12.73 0 top
NOREF#40  -  [unnamed]  0 10.1 0 top
NOREF#41  -  [#2]  -8.54 69.34 0 top
NOREF#42  -  [#2]  114.68 -68.88 0 top
NOREF#43  -  [unnamed]  27.28 63.17 180 top
NOREF#44  -  [unnamed]  108.69 43.56 180 top
NOREF#45  -  [unnamed]  0 54.07 0 top
NOREF#46  -  [unnamed]  114.68 61.34 0 top
NOREF#47  -  [unnamed]  108.69 16.11 180 top
NOREF#48  -  [#2]  50.92 159.95 0 top
NOREF#49  -  [#2]  11.73 -2.58 0 top
NOREF#50  -  [unnamed]  107.29 62.05 0 top
NOREF#51  -  [unnamed]  109.14 41.02 0 top
NOREF#52  -  [#2]  -1.27 -61.78 0 top
NOREF#53  -  [#2]  -1.27 15.18 0 top
NOREF#54  -  [#2]  -1.27 10.1 0 top
NOREF#55  -  [#2]  -2.54 -71.88 0 top
NOREF#56  -  [#2]  111.68 -71.88 0 top
NOREF#57  -  [unnamed]  28.3 0.95 0 top
NOREF#58  -  [unnamed]  109.14 13.57 0 top
NOREF#59  -  [unnamed]  27.28 6.17 180 top
NOREF#60  -  [#2]  202.3 71.42 0 top
NOREF#61  -  [#2]  -5.54 -68.88 0 top
NOREF#62  -  [unnamed]  25.79 1.6 180 top
NOREF#63  -  [unnamed]  78.9 1.35 180 top
NOREF#64  -  [#2]  170.66 212.8 0 top
NOREF#65  -  [#2]  115.67 61.49 0 top
NOREF#66  -  [#2]  95.96 -2.55 0 top
NOREF#67  -  [#2]  109.14 -63.28 0 top
NOREF#68  -  [#2]  -8.54 -71.88 0 top
NOREF#69  -  [unnamed]  23.27 1.36 0 top
NOREF#70  -  [unnamed]  109.14 46.1 0 top
NOREF#71  -  [#2]  -8.54 -71.88 0 top
NOREF#72  -  [unnamed]  108.69 14.84 180 top
NOREF#73  -  [#2]  27.28 156.98 0 top
NOREF#74  -  [#2]  -40.8 234.31 0 top
NOREF#75  -  [unnamed]  0.44 11.37 0 top
NOREF#76  -  [unnamed]  77.28 6.17 180 top
NOREF#77  -  [unnamed]  27.04 1.5 180 top
NOREF#78  -  [unnamed]  108.69 42.29 180 top
NOREF#79  -  [unnamed]  -5.54 61.34 0 top
NOREF#80  -  [#2]  -98.72 -141.99 0 top
NOREF#81  -  [#2]  117.68 -71.88 0 top
NOREF#82  -  [unnamed]  103.48 63.95 180 bottom
NOREF#83  -  [unnamed]  103.48 5.53 180 bottom
NOREF#84  -  [unnamed]  114.68 61.34 180 bottom
NOREF#85  -  [unnamed]  4.42 5.53 180 bottom
NOREF#86  -  [#2]  10.51 61.54 180 bottom
NOREF#87  -  [unnamed]  -5.54 61.34 180 bottom
NOREF#88  -  [unnamed]  -5.54 -63.88 180 bottom
OFF_SC1  TESTPAD  [TPC50D30]  42.01 62.43 180 bottom
OFF_SC2  TESTPAD  [TPC50D30]  39.72 62.43 180 bottom
P1  TSW-115-08-F-D-RA  [CNHDRRA2X15H224]  7.37 52.45 270 top
P510  FTSH-105-01-L-D  [CNHDR2X5H219]  58.39 2.99 0 top
P516  47590-0001  [CNMOLEX47590-0001]  109.14 34.67 180 top
P519  47590-0001  [CNMOLEX47590-0001]  109.14 52.45 180 top
Q1  BSS138LT1G  [SOT23]  96.11 35.38 0 bottom
Q2  BSS138LT1G  [SOT23]  82.78 5.66 180 bottom
Q3  IRLML5103TRPBF  [SOT23-M3]  51.28 39.51 180 bottom
Q4  IRLML5103TRPBF  [SOT23-M3]  21.69 12.52 90 bottom
Q5  IRLML5103TRPBF  [SOT23-M3]  25.37 12.52 90 bottom
Q8  BSS123LT1G  [SOT23]  30.96 28.65 0 bottom
Q9  BSS123LT1G  [SOT23]  30.96 33.73 0 bottom
Q512  BSS138LT1G  [SOT23]  99.73 35.38 0 bottom
R1  23.2K  [R0402]  54.84 20.14 180 bottom
R2  100K  [R0402]  56.61 21.41 0 top
R3  10K  [R0402]  57.63 53.79 0 top
R4  10K  [R0402]  57.63 52.91 180 top
R6  8.25K  [R0402]  71.09 65.1 90 top
R7  10.7K  [R0402]  50.52 14.55 270 bottom
R8  0  [R0402]  56.74 17.73 180 bottom
R9  2  [R0402]  59.15 10.61 180 top
R10  90.9K  [R0402]  50.52 12.77 270 bottom
R11  0  [R0402]  46.2 5.92 0 bottom
R12  0  [R0402]  46.2 7.44 180 bottom
R13  10K  [R0402]  55.85 48.46 180 top
R14  10K  [R0402]  59.09 39.25 270 bottom
R15  22  [R0201]  69.82 52.97 90 top
R16  820K  [R0805]  19.02 56.46 0 top
R17  200K  [R0603]  20.42 56.33 90 bottom
R18  21K  [R0603]  21.94 58.87 180 bottom
R19  820K  [R0805]  19.02 54.68 0 top
R20  200K  [R0603]  20.42 53.67 270 bottom
R21  21K  [R0603]  22.71 52.14 180 bottom
R22  4.99K  [R0402]  31.34 55.06 0 top
R23  4.99K  [R0402]  31.34 56.08 0 top
R24  10K  [R0402]  33.88 51.25 180 top
R25  10K  [R0402]  35.15 60.02 180 top
R26  3K  [R0402]  39.52 58.19 0 top
R27  3K  [R0402]  39.52 57.27 0 top
R28  3.9K  [R0402]  40.87 56.84 90 top
R29  3.9K  [R0402]  40.87 58.62 270 top
R30  11.3K  [R0402]  42.64 53.92 270 bottom
R31  11.3K  [R0402]  43.79 50.62 180 bottom
R32  4.99K  [R0402]  41.12 53.92 90 bottom
R33  4.99K  [R0402]  43.79 51.51 0 bottom
R34  3.9K  [R0402]  42.39 58.62 90 bottom
R35  3.9K  [R0402]  40.87 56.72 270 bottom
R36  33  [R0402]  48.23 56.97 0 bottom
R37  100  [R0402]  52.62 54.16 315 top
R38  100  [R0402]  51.99 53.53 315 top
R39  4.99  [R0402]  51.66 55.19 315 bottom
R40  4.99  [R0402]  50.9 54.43 315 bottom
R41  820K  [R0805]  19.02 42.75 0 top
R42  200K  [R0603]  20.55 42.36 270 bottom
R43  21K  [R0603]  21.18 39.7 270 bottom
R44  820K  [R0805]  19.02 44.52 0 top
R45  200K  [R0603]  20.55 44.9 90 bottom
R46  21K  [R0603]  21.31 47.32 90 bottom
R47  10K  [R0402]  36.8 38.94 180 top
R48  4.99K  [R0402]  31.34 44.14 0 top
R49  4.99K  [R0402]  31.34 43.13 0 top
R50  10K  [R0402]  35.15 48.08 180 top
R51  10K  [R0402]  33.88 39.19 180 top
R52  3K  [R0402]  39.52 46.25 0 top
R53  3K  [R0402]  39.52 45.34 0 top
R54  3.9K  [R0402]  40.87 44.9 90 top
R55  3.9K  [R0402]  40.87 46.68 270 top
R56  11.3K  [R0402]  41.12 41.98 270 bottom
R57  11.3K  [R0402]  43.53 38.68 180 bottom
R58  4.99K  [R0402]  42.64 41.98 90 bottom
R59  4.99K  [R0402]  43.53 39.57 0 bottom
R60  3.9K  [R0402]  42.39 46.68 90 bottom
R61  3.9K  [R0402]  40.87 44.78 270 bottom
R62  33  [R0402]  48.23 43.51 0 bottom
R63  100  [R0402]  49.76 46.05 0 top
R64  100  [R0402]  49.76 45.16 0 top
R65  4.99  [R0402]  49.19 46.11 0 bottom
R66  4.99  [R0402]  49.19 45.1 0 bottom
R67  3.83K  [R0402]  47.47 13.15 180 top
R68  1  [R0402]  45.82 4.52 270 top
R69  43.2K  [R0402]  47.6 11 270 bottom
R70  35.7K  [R0603]  36.93 11.25 0 bottom
R71  9.09K  [R0402]  33.5 13.66 90 bottom
R72  105K  [R0402]  34.01 12.27 180 bottom
R73  165K  [R0402]  47.6 12.77 90 bottom
R74  8.25K  [R0402]  82.01 58.11 180 top
R75  8.25K  [R0402]  79.98 58.11 0 top
R76  0  [R0402]  57.5 54.43 270 bottom
R77  69.8K  [R0402]  41.25 16.46 0 top
R78  120K  [R0402]  41.63 17.85 90 top
R79  1.6K  [R0402]  31.6 39.95 270 bottom
R80  1K  [R0402]  29.82 39.95 90 bottom
R81  4.02K  [R0402]  40.49 52.14 0 bottom
R82  1K  [R0402]  40.87 50.87 270 bottom
R83  470  [R0402]  66.34 64.36 180 top
R84  470  [R0402]  64.41 64.36 0 top
R85  4.7K  [R0402]  62.84 63.19 270 top
R86  22K  [R0402]  69.7 63.57 180 top
R87  10K  [R0402]  52.55 34.49 90 top
R88  10  [R0201]  77.57 58.24 270 top
R89  100K  [R0402]  86.59 53.92 180 top
R90  15K  [R0402]  81.89 57.86 180 bottom
R91  0  [R0402]  85.32 56.59 90 top
R92  82.5K  [R0402]  85.7 55.19 0 bottom
R93  124  [R0603]  38.58 24.08 0 top
R94  124  [R0603]  39.85 34.49 0 top
R95  124  [R0603]  36.29 24.08 180 top
R96  124  [R0603]  37.56 34.49 180 top
R97  0  [R0402]  32.87 22.93 90 top
R98  0  [R0402]  32.23 32.59 90 top
R99  3K  [R0603]  33.75 31.82 90 bottom
R100  3K  [R0603]  34.64 34.87 180 top
R101  470  [R0402]  32.87 24.71 90 top
R102  100  [R0402]  33.75 24.71 90 top
R103  470  [R0402]  34.01 33.35 90 top
R104  100  [R0402]  35.28 33.73 180 top
R105  1.47K  [R0603]  31.21 29.03 0 top
R106  1.47K  [R0603]  30.71 35.44 90 top
R107  2.21K  [R0402]  30.45 27.38 270 top
R108  2.21K  [R0402]  30.33 33.35 270 top
R109  22  [R0201]  71.22 43.83 180 top
R110  22  [R0201]  71.22 42.11 180 top
R111  22  [R0201]  69.38 43.25 180 top
R112  22  [R0201]  69.38 44.4 180 top
R113  22  [R0201]  71.22 44.97 180 top
R114  22  [R0201]  69.38 45.54 180 top
R115  2K  [R0402]  54.9 30.55 270 top
R116  10K  [R0402]  53.95 30.55 90 top
R117  1.47K  [R0603]  52.55 29.35 180 bottom
R118  1.47K  [R0603]  50.58 27.89 270 bottom
R119  10K  [R0402]  38.58 27.51 0 bottom
R120  10K  [R0402]  40.36 27.51 0 bottom
R121  3.9K  [R0402]  43.53 36.14 270 top
R122  3.9K  [R0402]  51.28 36.65 270 top
R123  1.47K  [R0603]  50.77 31.44 180 top
R124  1.47K  [R0603]  43.03 32.33 270 top
R125  1.3K  [R0402]  43.53 34.49 270 top
R126  1.3K  [R0402]  49.5 35 270 top
R127  2.49K  [R0402]  49.5 29.79 270 top
R128  2.49K  [R0402]  43.91 30.17 270 top
R129  20K  [R0402]  22.45 14.81 180 bottom
R130  10K  [R0402]  94.97 34.17 90 top
R131  20K  [R0402]  48.99 40.59 90 bottom
R132  49.9  [R1206]  24.04 27.25 270 top
R133  49.9  [R1206]  24.04 32.65 270 top
R134  8.06K  [R0402]  22.2 32.65 270 top
R135  8.06K  [R0402]  22.2 26.24 90 top
R136  2K  [R0402]  56.68 25.22 270 top
R137  4.02K  [R0402]  11.28 13.73 270 bottom
R138  4.02K  [R0402]  9.94 13.28 180 bottom
R139  4.02K  [R0402]  56.68 26.81 270 top
R140  10K  [R0402]  26.26 18.62 180 bottom
R141  10K  [R0402]  24.48 18.62 180 bottom
R142  10K  [R0402]  22.26 18.23 180 top
R143  100  [R0402]  50.71 27.95 90 top
R144  10K  [R0402]  34.9 28.39 0 bottom
R145  20K  [R0402]  103.22 24.97 0 top
R147  20K  [R0402]  25.75 10.23 180 bottom
R148  4.99K  [R0402]  93.06 34.49 180 top
R149  0  [R0402]  76.3 55.95 180 top
R150  0  [R0402]  21.69 23.44 90 top
R151  0  [R0402]  22.58 23.44 90 top
R152  0  [R0402]  20.8 23.44 270 top
R153  0  [R0402]  23.47 23.44 270 top
R154  20K  [R0402]  15.59 47.19 0 bottom
R155  4.7K  [R0402#2]  35.15 9.6 0 bottom
R156  10K  [R0402]  102.02 38.55 0 top
R158  1K  [R0402]  16.48 14.55 180 top
R159  1K  [R0402]  16.48 8.84 180 top
R160  5.1K  [R0402]  14.58 8.84 180 top
R161  4.02K  [R0402]  14.58 14.55 180 top
R162  4.7  [R0805]  12.29 14.04 90 top
R163  4.7  [R0805]  12.29 7.95 90 top
R164  15K  [R0402]  31.66 63.64 90 bottom
R165  6.49K  [R0402#2]  32.1 65.1 0 bottom
R166  27.4K  [R0402]  103.29 57.54 45 bottom
R167  22  [R0201]  71.22 46.11 180 top
R168  22  [R0201]  69.38 46.68 180 top
R169  22  [R0201]  71.22 47.25 180 top
R170  22  [R0201]  69.38 47.7 180 top
R171  22  [R0201]  69.38 48.59 180 top
R172  22  [R0201]  71.22 48.4 180 top
R173  22  [R0201]  85.32 37.67 90 bottom
R174  22  [R0201]  71.16 41.09 0 top
R175  22  [R0201]  69.38 42.11 0 top
R176  22  [R0201]  81.63 37.67 270 bottom
R177  22  [R0201]  90.4 37.67 270 bottom
R178  22  [R0201]  87.86 37.67 270 bottom
R179  22  [R0201]  91.41 37.67 270 bottom
R180  22  [R0201]  90.9 35.63 270 bottom
R181  22  [R0201]  84.3 37.67 270 bottom
R182  22  [R0201]  86.33 37.67 270 bottom
R183  22  [R0201]  87.86 35.63 270 bottom
R184  22  [R0201]  88.87 37.67 270 bottom
R185  22  [R0201]  88.87 35.63 270 bottom
R186  22  [R0201]  89.89 35.63 270 bottom
R187  22  [R0201]  82.65 37.67 270 bottom
R188  22  [R0201]  86.33 35.63 270 bottom
R189  100  [R0402]  104.49 57.54 45 bottom
R190  8.06K  [R0402]  105.7 58.75 45 bottom
R191  240  [R0402]  102.65 59.19 45 bottom
R192  470  [R0402]  103.92 60.46 45 bottom
R193  11K  [R0402]  30.83 32.08 180 top
R194  11K  [R0402]  30.96 25.98 180 top
R195  10K  [R0402]  99.29 62.81 315 bottom
R196  10K  [R0402]  100.05 63.57 315 bottom
R197  1K  [R0402]  22.2 28.01 90 top
R198  1K  [R0402]  22.2 31.06 270 top
R199  20K  [R0402]  29.94 31.19 180 bottom
R200  20K  [R0402]  33.5 34.11 90 bottom
R201  10K  [R0402]  29.69 25.22 90 top
R202  10K  [R0402]  28.8 33.73 90 bottom
R203  47.5K  [R0402]  76.81 56.97 0 top
R204  4.99K  [R0402]  80.24 56.21 270 bottom
R205  0  [R0402]  76.81 48.4 90 bottom
R206  0  [R0402]  78.33 54.94 270 bottom
R207  16.2K  [R0402]  85.7 48.59 90 bottom
R208  24.3K  [R0402]  83.03 54.94 270 bottom
R209  0  [R0402]  58.27 10.49 180 bottom
R210  4.7K  [R0402]  78.2 29.54 315 bottom
R211  4.7K  [R0402]  76.43 31.32 315 bottom
R212  10K  [R0402]  105 42.87 270 bottom
R213  2.49K  [R0402]  93.06 35.51 0 top
R214  20K  [R0402]  85.06 4.65 90 bottom
R215  470  [R0402]  85.06 6.55 90 bottom
R216  0  [R0402]  80.43 15.06 90 bottom
R217  0  [R0402]  74.52 31.13 270 bottom
R517  10  [R0201]  91.29 54.18 0 top
R581  33  [R0402#2]  76.33 17.69 45 top
R583  20K  [R0402]  72.49 5.28 0 bottom
R584  20K  [R0402]  76.93 21.11 45 bottom
R585  20K  [R0402]  68.97 13.92 135 bottom
R586  240  [R0402]  72.49 6.3 180 bottom
R587  0  [R0402]  70.41 15.35 315 bottom
R590  20K  [R0402]  69.44 7.19 0 bottom
R591  20K  [R0402]  67.54 8.71 90 bottom
R592  20K  [R0402]  77.77 14.46 315 top
R593  20K  [R0402]  70.08 9.6 90 bottom
R594  20K  [R0402]  71.09 9.6 90 bottom
R601  120  [R0201]  101.43 11.63 315 bottom
R602  120  [R0201]  103.34 16.22 45 bottom
R603  120  [R0201]  100.37 19.77 45 bottom
R604  120  [R0201]  97.04 20.26 135 bottom
R605  120  [R0201]  98.95 21.18 45 bottom
R606  120  [R0201]  94.85 18.07 135 bottom
R608  120  [R0201]  101.5 18.63 45 bottom
R609  120  [R0201]  101.99 12.2 315 bottom
R610  120  [R0201]  102.56 12.76 315 bottom
R611  120  [R0201]  104.11 14.32 315 bottom
R612  120  [R0201]  104.26 16.01 45 bottom
R613  120  [R0201]  99.8 20.33 45 bottom
R619  120  [R0201]  100.93 19.2 45 bottom
R620  120  [R0201]  95.98 19.2 135 bottom
R621  120  [R0201]  95.41 18.64 135 bottom
R622  120  [R0201]  99.3 13.33 45 bottom
R623  120  [R0201]  98.17 14.46 45 bottom
R624  120  [R0201]  99.73 9.93 315 bottom
R625  80.6  [R0402]  96.3 13.73 45 bottom
R627  120  [R0201]  103.12 17.15 45 bottom
R628  120  [R0201]  100.86 11.06 315 bottom
R629  120  [R0201]  97.61 15.03 45 bottom
R630  120  [R0201]  98.74 13.89 45 bottom
R631  120  [R0201]  94.28 17.5 135 bottom
R632  120  [R0201]  100.29 10.5 315 bottom
R634  240  [R0402]  88.75 21.61 315 bottom
R635  240  [R0402]  86.98 23.52 315 bottom
R636  1K  [R0402]  104.98 15.44 45 bottom
R638  10K  [R0402]  98.27 32.9 0 top
R640  10K  [R0402]  99.29 31.7 45 bottom
R642  0  [R0402]  102.78 29.09 135 bottom
R653  0  [R0402]  101.49 28.84 45 top
R661  240  [R0402]  92.75 18.17 135 bottom
R681  0  [R0402]  78.63 22.39 45 bottom
R685  4.7K  [R0402]  89.89 31.95 45 bottom
R689  4.7K  [R0402]  78.85 15.53 315 top
R691  470  [R0402]  106.02 21.92 90 top
R743  27.4K  [R0402]  96.75 55.95 180 top
R744  1K  [R0402#2]  106.53 40.59 180 top
R747  4.7K  [R0402]  95.48 53.92 270 bottom
R749  1K  [R0402#2]  107.1 58.75 90 top
R750  20K  [R0402]  98.4 51 270 bottom
R752  10K  [R0402]  98.02 54.94 0 bottom
R760  10K  [R0402]  92.56 55.57 270 bottom
R763  17.8K  [R0603]  88.62 41.48 90 bottom
R764  14.3K  [R0201]  91.41 53.41 180 bottom
R765  46.4K  [R0402]  98.27 45.67 270 bottom
R766  23.2K  [R0402]  98.02 53.41 0 bottom
R791  10K  [R0402]  73.51 21.28 45 top
R797  33  [R0402]  60.81 28.52 180 top
R798  20K  [R0402]  77.64 25.08 225 bottom
R800  8.06K  [R0402]  60.42 30.17 90 bottom
RT1  220  [R0603H35]  16.99 38.43 180 bottom
RT2  220  [R0603H35]  16.99 35.89 180 bottom
RT3  220  [R0603H35]  16.99 33.35 180 bottom
RT4  220  [R0603H35]  16.99 30.81 180 bottom
RT5  220  [R0603H35]  16.99 28.27 180 bottom
RT6  220  [R0603H35]  16.99 25.73 180 bottom
RT7  220  [R0603H35]  16.99 23.19 180 bottom
RT8  220  [R0603H35]  16.99 20.65 180 bottom
RT9  220  [R0603H35]  16.99 18.11 180 bottom
RT10  220  [R0603H35]  16.99 37.16 0 bottom
RT11  220  [R0603H35]  16.99 34.62 0 bottom
RT12  220  [R0603H35]  16.99 32.08 0 bottom
RT13  220  [R0603H35]  16.99 29.54 0 bottom
RT14  220  [R0603H35]  16.99 27 0 bottom
RT15  220  [R0603H35]  16.99 24.46 0 bottom
RT16  220  [R0603H35]  16.99 21.92 0 bottom
RT17  220  [R0603H35]  16.99 19.38 0 bottom
RT18  220  [R0603H35]  16.99 16.84 0 bottom
RX  TESTPAD  [TPSMC40]  57.76 6.17 180 bottom
S1  PTS840 GKP SMTR LFS  [SWSML140W138H55]  106.53 25.78 0 top
TCK  TESTPAD  [TPSMC40]  60.3 6.17 180 bottom
TDI  TESTPAD  [TPSMC40]  62.84 6.17 180 bottom
TDO  TESTPAD  [TPSMC40]  62.84 8.71 180 bottom
TMS  TESTPAD  [TPSMC40]  60.3 8.71 180 bottom
TP5  TESTPAD  [TPC50D30]  24.99 16.58 180 bottom
TP6  TESTPAD  [TPC50D30]  72.49 63.45 180 bottom
TP7  TESTPAD  [TPC50D30]  21.94 62.75 180 bottom
TX  TESTPAD  [TPSMC40]  57.76 8.71 180 bottom
U2  AD9963BCPZ  [QFN72_10X10_PAD7_1X7_1]  62.84 46.81 270 top
U3  ADA4940-2ACPZ  [QFN24_4X4_PAD2_5X2_5]  44.8 55.19 270 top
U4  ADA4940-2ACPZ  [QFN24_4X4_PAD2_5X2_5]  44.8 43.25 270 top
U6  ADP2114ACPZ  [QFN32_5X5_PAD3_1X3_1]  80.87 53.79 180 top
U7  ADP2370ACPZ-R7  [QFN8_3X3_PAD2_44X1_7]  36.8 13.03 180 top
U8  ADG1404YCPZ  [QFN16_4X4_PAD2_5X2_5]  36.68 49.48 90 bottom
U9  ADG1404YCPZ  [QFN16_4X4_PAD2_5X2_5]  35.79 37.67 90 bottom
U10  ADP5074ACPZ  [QFN16_3X3_PAD1_7X1_7]  54.84 18.62 90 top
U11  AD5625BRUZ  [TSSOP14]  39.85 30.93 90 bottom
U12  ADP1614ACPZ  [QFN10_3X3_PAD2_38X1_64]  45.95 8.96 180 top
U13  ADP7182ACPZ-R7  [QFN8_3X3_PAD2_44X1_7]  44.68 17.98 270 top
U14  ADF4360-9BCPZ  [QFN24_4X4_PAD2_3X2_3]  65.38 59.51 90 top
U15  ADP5589ACPZ-00  [QFN24_3_5X3_5_PAD2_2X2_2]  55.6 35.25 90 top
U16  ADP198ACBZ-11  [WLCSP4-2]  105 45.92 180 top
U17  LT1761ES5-SD#TRMPBF  [TSOT-5]  33.5 64.21 90 top
U18  ADR3412ARJZ  [SOT23_6-2]  41.5 23.44 270 bottom
U19  ADR3412ARJZ  [SOT23_6-2]  34.14 24.33 270 bottom
U20  AD5627BRMZ  [RM10]  22.45 20.65 270 top
U21  LTC4415EDHC#PBF  [DFN16_5X3_PAD4_4X1_65]  102.21 60.91 45 top
U508  MT25QU256ABA8E12-1SIT  [TBGA24]  69.7 6.8 90 top
U509  TPS51206DSQR  [SON10_2X2_PAD1_5X0_9]  100.68 31.44 45 top
U511  XC7Z010-1CLG225C4334  [CSPBGA225]  83.16 26.49 45 top
U518  ADP2114ACPZ  [QFN32_5X5_PAD3_1X3_1]  95.6 51.51 180 top
U524  USB3320C-EZK  [QFN32_5X5_PAD3_3X3_3]  62.58 32.2 90 top
U646  MT41K256M16TW-107:P  [FBGA96_C]  95.91 12.48 45 top
UNK1V8_D  TESTPAD  [TPSMC40]  97.25 42.3 180 bottom
UNK1V35  TESTPAD  [TPSMC40]  95.6 39.76 180 bottom
UNK3V3_A  TESTPAD  [TPSMC40]  28.67 15.06 180 bottom
UNK3V3_D  TESTPAD  [TPSMC40]  65.38 6.17 180 bottom
UNK4V0_A  TESTPAD  [TPSMC40]  37.44 61.41 180 bottom
UNK6V0_A  TESTPAD  [TPSMC40]  46.45 15.44 180 bottom
UNK-3V3_A  TESTPAD  [TPSMC40]  40.74 20.27 180 bottom
UNK-6V0_A  TESTPAD  [TPSMC40]  58.52 13.15 180 bottom
VCCPINT  TESTPAD  [TPSMC40]  79.98 42.36 180 bottom
VIN  TESTPAD  [TPSMC40]  86.65 62.94 180 bottom
VR1  LT1964ES5-5#TRPBF  [TSOT-5]  16.61 49.48 270 bottom
Y1  20MHZ  [YSML197W126H59-2]  59.28 63.83 270 top
Y523  24MEGHZ  [YSML98W79H35]  59.6 26.55 0 top
Y578  33.333MEGHZ  [YSML98W79H35]  74.09 14.55 45 top

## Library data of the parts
A1 A4 = ADG202N: Tolerance: N/A; User Part Number: UPN; alternate symbols: (); part number: ADG202N_SM-ADG612YRUZ,E006320,TSSOP16; tolerance: N/A
A2 = ADG202N: Tolerance: N/A; User Part Number: UPN; alternate symbols: (); part number: ADG202N_SM-ADG611YRUZ,E022133,TSSOP16; tolerance: N/A
A3 A5 = AD8066: Tolerance: N/A; User Part Number: UPN; alternate symbols: (); part number: AD8066_SM-AD8066ARZ,E004991,SO8; tolerance: N/A
A6 A8 A11 A13 = AD8657_V2: Tolerance: N/A; User Part Number: UPN; alternate symbols: (); part number: AD8657_V2_SM-AD8657ACPZ,E019277,QFN8_3X3_PAD2_44X1_7; tolerance: N/A
A7 A9 = AD8000: User Part Number: UPN; Tolerance: N/A; alternate symbols: (); part number: AD8000_SM-AD8000YCPZ-R2,E006723,QFN8_3X3_PAD1_75X1_45; tolerance: N/A
A10 = ADOPAMP2: Tolerance: N/A; User Part Number: UPN; alternate symbols: (); part number: ADOPAMP2_SM-AD8058ARZ,E013610,SO8; tolerance: N/A
A12 A14 = ADA4805_1: Tolerance: N/A; User Part Number: UPN; alternate symbols: (); part number: ADA4805_1_SM-ADA4805-1AKSZ,E018212,SC70-6; tolerance: N/A
C1 = CAP: Tolerance: 10; User Part Number: UPN; alternate symbols: C0402L_ALT; part number: CAP_SM-2200PF,50V,10,E024338,C0402; tolerance: 10
C2 = CAP: Tolerance: 20; User Part Number: UPN; alternate symbols: (); part number: CAP_SM-10UF,10V,20,E022682,C0603; tolerance: 20
C3 C6 C16 C29-C33 C47 C67 C80 C81 C87 C90 C98 C107 C108 C124 C133 C137 C138 C144 C148 C152 C156 C157 C175 C179 C196 C204-C206 C209-C214 C221 C222 C228 C244 C245 C262 C263 C272 C273 C284 C285 C297 C308 C310 C311 C316 C317 C330 C333 C748 C805 C807 = CAP: Tolerance: 20; User Part Number: UPN; alternate symbols: C0402L_ALT; part number: CAP_SM-1UF,16V,20,E020695,C0402; tolerance: 20
C4 C7 C44 C49-C51 C53-C62 C65 C68 C79 C82 C86 C91 C96 C97 C100 C109-C116 C125 C136 C139 C142 C150 C151 C158-C161 C164-C167 C180 C202 C216 C219 C220 C224 C229 C231 C232 C240 C246 C247 C250 C251 C264 C265 C274 C275 C286-C288 C292-C294 C296 C299 C300 C306 C307 C318 C319 C324 C331 C334 = CAP: User Part Number: UPN; Tolerance: 20; alternate symbols: (); part number: CAP_SM-0.1UF,16V,20,E017331,C0201; tolerance: 20
C5 C19 C177 C186 C191 C192 C195 C198 C215 = CAP: Tolerance: 20; User Part Number: UPN; alternate symbols: (); part number: CAP_SM-22UF,25V,20,E032575,C0805H60; tolerance: 20
